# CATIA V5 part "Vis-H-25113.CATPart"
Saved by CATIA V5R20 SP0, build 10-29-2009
Part number: Vis-H-M5x18
Definition: Vis-H-M5
Description: Vis-H-M3x14
Material "Inox": density 7900 kg/m3, Young's modulus 2e+11 Pa, Poisson ratio 0.266, thermal expansion 1.17e-05 1/K
Bounding box of the stored display mesh (mm): x 0 to 21.5, y -4.619 to 4.619, z -4 to 4
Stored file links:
  C:\travail\CATIA\visserie\ecrous H\catdua\Vis-H-25113.CATPart
  C:\travail\CATIA\visserie\vis-h-NFE25113.xls
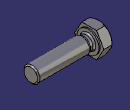
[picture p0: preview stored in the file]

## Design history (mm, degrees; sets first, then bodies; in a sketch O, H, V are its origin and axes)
External parameters (linked from other documents)
  External.S = 8 mm {design table}
  External.K = 3.5 mm {design table}
  External.Dn = 5 mm {design table}
  External.i = 18 mm {design table}
  External.TARAUDAGE = "M5" {design table}
  External.PAS = 0.8 mm {design table}
  External.Dw = 6.9 mm {design table}
  External.B = 16 mm {design table}
  External.Norme = "NF E25.113" {design table}
  External.Ds = 4.4 mm {design table}
Set1 "ref"
  Sketch1 on yz-plane, origin (0, 0, 0), H (0, 1, 0), V (0, 0, 1)
    construction circle A1 centre (0, 0) radius 4.6188
    point P1 (2.3094, 4)
    line L1 (2.3094, 4) -> (-2.3094, 4)
    point P2 (-2.3094, 4)
    line L2 (-2.3094, 4) -> (-4.6188, 0)
    point P3 (-4.6188, 0)
    line L3 (-4.6188, 0) -> (-2.3094, -4)
    point P4 (-2.3094, -4)
    line L4 (-2.3094, -4) -> (2.3094, -4)
    point P5 (2.3094, -4)
    line L5 (2.3094, -4) -> (4.6188, 0)
    point P6 (4.6188, 0)
    line L6 (4.6188, 0) -> (2.3094, 4)
    axis line L7 (0, 0) -> (-7.0289, 12.1744)
    angle H L7 = 60
    distance L5 L2 = 8 {= External.S}
    coincidence: P1 A1, P2 A1, P3 A1, P4 A1, P5 A1, P6 A1, P2 L7, P3 H, P5 L7, P6 H
    horizontal: L1 H, L4 H
Body1 (main body)
  Sketch2 on yz-plane, origin (0, 0, 0), H (0, 1, 0), V (0, 0, 1)
    circle A1 centre (0, 0) radius 4.6188
    point P1 (4.6188, 0)
    line L1 (4.6188, 0) -> (2.3094, 4)
    point P2 (2.3094, 4)
    line L2 (2.3094, 4) -> (-2.3094, 4)
    point P3 (-2.3094, 4)
    line L3 (-2.3094, 4) -> (-4.6188, 0)
    point P4 (-4.6188, 0)
    line L4 (-4.6188, 0) -> (-2.3094, -4)
    point P5 (-2.3094, -4)
    line L5 (-2.3094, -4) -> (2.3094, -4)
    point P6 (2.3094, -4)
    line L6 (2.3094, -4) -> (4.6188, 0)
    distance L1 L4 = 8 {= Sketch2.distance(L2 L5)}
    distance L2 L5 = 8 {= External.S}
    radius A1 = 4.6188 (reference)
    coincidence: P1 A1, P1 H, P2 A1, P3 A1, P4 A1, P4 H, P5 A1, P6 A1
    horizontal: L2 H, L5 H
  Sketch3 on xy-plane, origin (0, 0, 0), H (1, 0, 0), V (0, 1, 0)
    point P1 (0, 4.6188)
    line L1 (0, 4.6188) -> (3.1, 4.6188)
    line L2 (3.1, 4.6188) -> (3.1, 3.45)
    line L3 (3.1, 3.45) -> (3.5, 3.45)
    line L4 (3.5, 3.45) -> (3.5, 2.5)
    point P5 (3.5, 2.5)
    line L5 (21.5, 2.5) -> (21.5, 0)
    point P7 (21.5, 0)
    axis line L6 (12.3935, 0) -> (-2.3152, 0)
    point P8 (12.3935, 0)
    reference projected point E1 (0, 4.6188) from vertex [element of Sketch2 | element of Sketch2]
    line L7 (0, 4.6188) -> (0, 0)
    arc A1 centre (4.1245, 3) radius 0.8 from (3.5, 2.5) to (4.1245, 2.2) ccw
    line L8 (4.1245, 2.2) -> (4.8755, 2.2)
    arc A2 centre (4.8755, 3) radius 0.8 from (4.8755, 2.2) to (5.5, 2.5) ccw
    line L9 (5.5, 2.5) -> (21.5, 2.5)
    "Radius" L3 L6 = 3.45 {= External.Dw /2}
    distance L7 L4 = 3.5 {= External.K}
    distance L4 L2 = 0.4 {= External.PAS /2}
    distance L4 L5 = 18 {= External.i}
    "Radius" L8 L6 = 2.2 {= External.Ds /2}
    "Radius" L9 L6 = 2.5 {= External.Dn /2}
    length L9 = 16 {= External.B}
    radius A1 = 0.8 {= External.PAS}
    radius A2 = 0.8 {= External.PAS}
    coincidence: P1 V, P7 H, P8 H, E1 P1, L9 P5
    horizontal: L1 H, L3 H, L6 H, L8 H
    vertical: L2 V, L4 V, L5 V, L7 V
    tangency: A1 L8, A2 L8
  Shaft1: profile Sketch3, axis Sketch3.L6, angle 360
  Chamfer1: length 0.6188 {= Sketch2.radius(A1) -Sketch2.distance(L2 L5) /2}, angle 45, on edge [face of Shaft1 from Sketch3.L1 | face of Shaft1 from Sketch3.L7]
  Pocket1: profile Sketch1, direction (-1, 0, 0), through (limit type 6), outer side
  Chamfer2: length 0.4 {= External.PAS /2}, angle 45, on edge [face of Shaft1 from Sketch3.L5 | face of Shaft1 from Sketch3.L9]
  Thread1: "M3", diameter 5 {= External.Dn}, depth 16 {= External.B}, pitch 0.5, on face of Shaft1 from Sketch3.L9, from face of Shaft1 from Sketch3.L5
Relations
  design table, configuration 18, drives External.Dn, External.Dw, External.B, External.K, External.Ds, External.S, External.Norme, External.i, External.PAS, External.TARAUDAGE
